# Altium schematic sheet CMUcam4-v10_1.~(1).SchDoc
size 249 x 186 mm
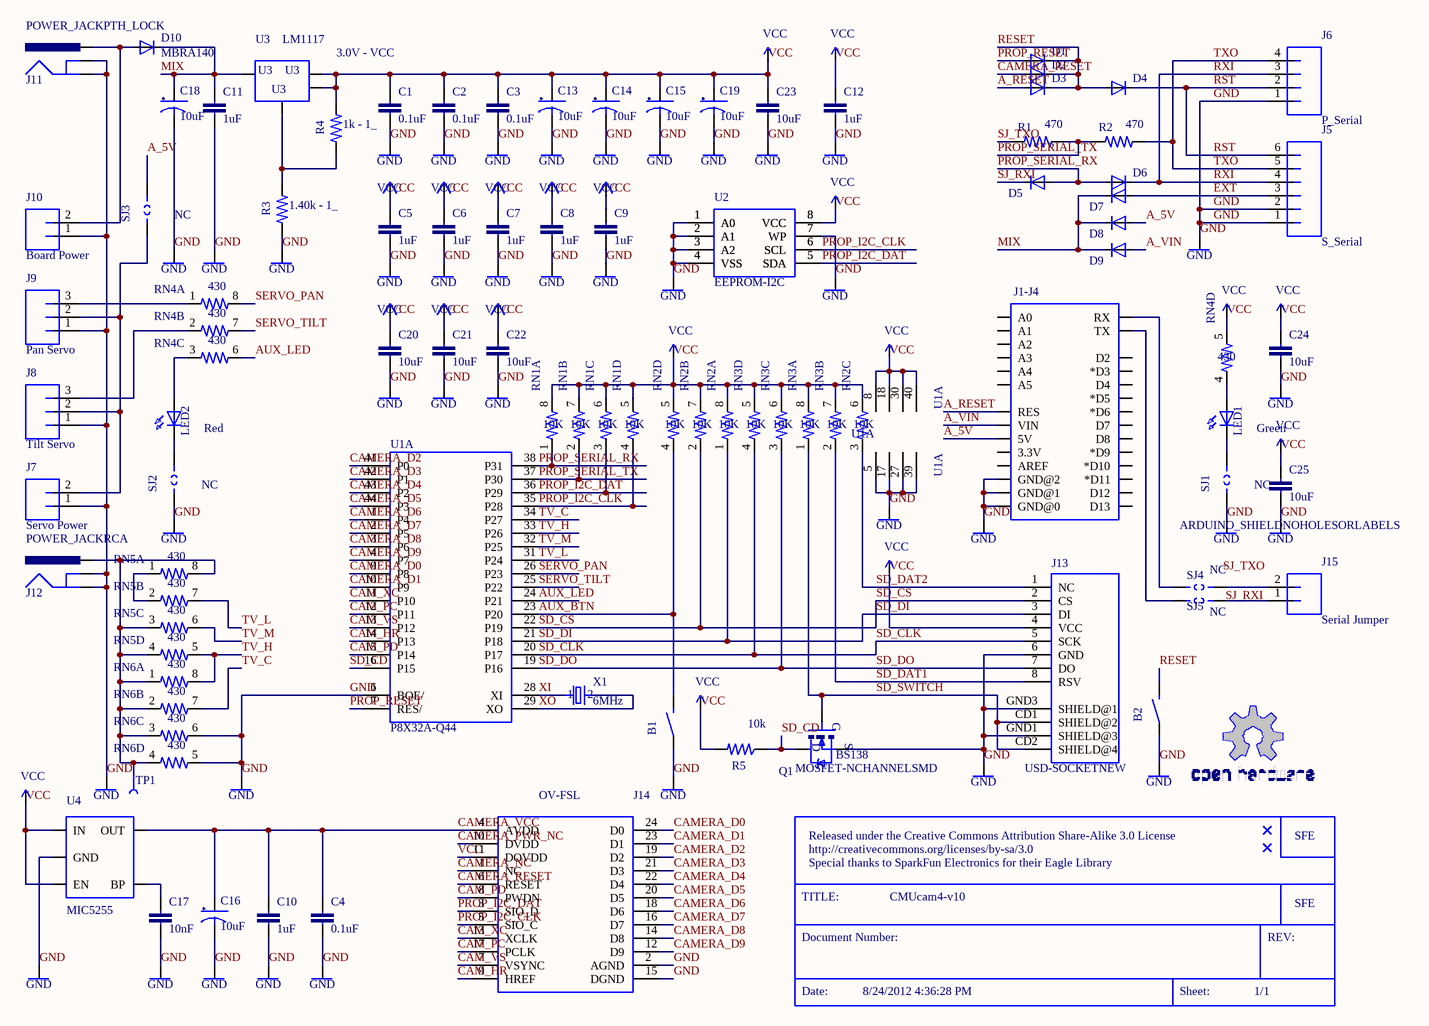
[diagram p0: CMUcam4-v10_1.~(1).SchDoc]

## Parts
(Parts that share a designator on the sheet are numbered #1, #2 ... from top to bottom, then left to right.)
B1  (no value)  [TACTILE_SWITCH_SMD]
B2  (no value)  [TACTILE_SWITCH_SMD]
C1  0.1uF  [0402-CAP]
C2  0.1uF  [0402-CAP]
C3  0.1uF  [0402-CAP]
C4  0.1uF  [0402-CAP]
C5  1uF  [0402-CAP]
C6  1uF  [0402-CAP]
C7  1uF  [0402-CAP]
C8  1uF  [0402-CAP]
C9  1uF  [0402-CAP]
C10  1uF  [0402-CAP]
C11  1uF  [0402-CAP]
C12  1uF  [0402-CAP]
C13  10uF  [EIA3216]
C14  10uF  [EIA3216]
C15  10uF  [EIA3216]
C16  10uF  [EIA3216]
C17  10nF  [0402-CAP]
C18  10uF  [EIA3216]
C19  10uF  [EIA3216]
C20  10uF  [0402-CAP]
C21  10uF  [0402-CAP]
C22  10uF  [0402-CAP]
C23  10uF  [0402-CAP]
C24  10uF  [0402-CAP]
C25  10uF  [0402-CAP]
D1  (no value)  [SOD523]
D2  (no value)  [SOD523]
D3  (no value)  [SOD523]
D4  (no value)  [SOD523]
D5  (no value)  [SOD523]
D6  (no value)  [SOD523]
D7  (no value)  [SMA-DIODE]
D8  (no value)  [SMA-DIODE]
D9  (no value)  [SMA-DIODE]
D10  MBRA140  [SMA-DIODE]
FRAME1  (no value)  (parts A,B of 2)
GND1  GND
GND2  GND
GND3  GND
GND4  GND
GND5  GND
GND6  GND
GND7  GND
GND8  GND
GND9  GND
GND10  GND
GND11  GND
GND12  GND
GND13  GND
GND14  GND
GND15  GND
GND16  GND
GND17  GND
GND18  GND
GND19  GND
GND20  GND
GND21  GND
GND22  GND
GND23  GND
GND24  GND
GND25  GND
GND26  GND
GND27  GND
GND28  GND
GND29  GND
GND30  GND
GND31  GND
GND32  GND
GND33  GND
GND34  GND
GND35  GND
GND36  GND
GND37  GND
GND38  GND
GND39  GND
J1-J4  ARDUINO_SHIELDNOHOLESORLABELS  [DUEMILANOVE_SHIELD_NOHOLES_NOLABELS]
J5  S_Serial  [1X06]
J6  P_Serial  [1X04]
J7  Servo Power  [1X02]
J8  Tilt Servo  [1X03]
J9  Pan Servo  [1X03]
J10  Board Power  [1X02]
J11  POWER_JACKPTH_LOCK  [POWER_JACK_PTH_LOCK]
J12  POWER_JACKRCA  [RCA]
J13  USD-SOCKETNEW  [MICRO-SD-SOCKET-PP]
J14  OV-FSL  [OV-FSL]
J15  Serial Jumper  [1X02]
JP1  (no value)  [SFE-NEW-WEBLOGO]
JP2  (no value)  [SFE-LOGO-FLAME]
JP3  (no value)  [MICRO-FIDUCIAL]
JP4  (no value)  [MICRO-FIDUCIAL]
LED1  Green  [LED-0603]
LED2  Red  [LED-0603]
P1  VCC
P2  VCC
P3  VCC
P4  VCC
P5  VCC
P6  VCC
P7  VCC
P8  VCC
P9  VCC
P10  VCC
P11  VCC
P12  VCC
P13  VCC
P14  VCC
P15  VCC
P16  VCC
P17  VCC
P18  VCC
P19  VCC
Q1  MOSFET-NCHANNELSMD  [SOT23-3]
R1  470  [0402-RES]
R2  470  [0402-RES]
R3  1.40k - 1_  [0402-RES]
R4  1k - 1_  [0402-RES]
R5  10k  [0402-RES]
RN1  10K  [0603-ARV]  (parts A,B,C,D of 4)
RN2  10K  [0603-ARV]  (parts A,B,C,D of 4)
RN3  10K  [0603-ARV]  (parts A,B,C,D of 4)
RN4  430  [0603-ARV]  (parts A,B,C,D of 4)
RN5  430  [0603-ARV]  (parts A,B,C,D of 4)
RN6  430  [0603-ARV]  (parts A,B,C,D of 4)
SJ1  NC  [SJ_2S-TRACE]
SJ2  NC  [SJ_2S-TRACE]
SJ3  NC  [SJ_2S-NO]
SJ4  NC  [SJ_2S-TRACE]
SJ5  NC  [SJ_2S-TRACE]
STD1  (no value)  [STAND-OFF]
STD2  (no value)  [STAND-OFF]
STD3  (no value)  [STAND-OFF]
STD4  (no value)  [STAND-OFF]
TP1  (no value)  [PAD.03X.03]
U1#1  (no value)  [P8X32A-Q44]  (part A of 2)
U1#2  P8X32A-Q44  [P8X32A-Q44]  (part A of 2)
U2  EEPROM-I2C  [SO08-EIAJ]
U3  LM1117  [SOT223]
U4  MIC5255  [SOT23-5]
U$1  (no value)  [OSHW-LOGO-M]
X1  6MHz  [HC49UP]

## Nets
A_5V: D8.A J1-J4.5V SJ3.2
A_RESET: D3.A J1-J4.RES
A_VIN: D9.A J1-J4.VIN
AUX_BTN: B1.3 RN2.4 U1#2.23(P20)
AUX_LED: RN4.6 U1#2.24(P21)
CAM_HR: J14.9(HREF) U1#2.14(P13)
CAM_PC: J14.17(PCLK) U1#2.12(P11)
CAM_PD: J14.8(PWDN) U1#2.15(P14)
CAM_VS: J14.7(VSYNC) U1#2.13(P12)
CAM_XC: J14.13(XCLK) U1#2.11(P10)
CAMERA_D0: J14.24(D0) U1#2.9(P8)
CAMERA_D1: J14.23(D1) U1#2.10(P9)
CAMERA_D2: J14.19(D2) U1#2.41(P0)
CAMERA_D3: J14.21(D3) U1#2.42(P1)
CAMERA_D4: J14.22(D4) U1#2.43(P2)
CAMERA_D5: J14.20(D5) U1#2.44(P3)
CAMERA_D6: J14.18(D6) U1#2.1(P4)
CAMERA_D7: J14.16(D7) U1#2.2(P5)
CAMERA_D8: J14.14(D8) U1#2.3(P6)
CAMERA_D9: J14.12(D9) U1#2.4(P7)
CAMERA_NC: J14.1(NC)
CAMERA_PWR_NC: J14.10(DVDD)
CAMERA_RESET: D2.A J14.6(RESET)
CAMERA_VCC: C4.1 C10.1 C16.A(+) J14.4(AVDD) U4.5(OUT)
EXT: D7.A J5.3
GND: B1.1 B2.1 C1.2 C2.2 C3.2 C4.2 C5.2 C6.2 C7.2 C8.2 C9.2 C10.2 C11.2 C12.2 C13.C(-) C14.C(-) C15.C(-) C16.C(-) C17.2 C18.C(-) C19.C(-) C20.2 C21.2 C22.2 C23.2 C24.2 C25.2 GND1.0(GND) GND2.0(GND) GND3.0(GND) GND4.0(GND) GND5.0(GND) GND6.0(GND) GND7.0(GND) GND8.0(GND) GND9.0(GND) GND10.0(GND) GND11.0(GND) GND12.0(GND) GND13.0(GND) GND14.0(GND) GND15.0(GND) GND16.0(GND) GND17.0(GND) GND18.0(GND) GND19.0(GND) GND20.0(GND) GND21.0(GND) GND22.0(GND) GND23.0(GND) GND24.0(GND) GND25.0(GND) GND26.0(GND) GND27.0(GND) GND28.0(GND) GND29.0(GND) GND30.0(GND) GND31.0(GND) GND32.0(GND) GND33.0(GND) GND34.0(GND) GND35.0(GND) GND36.0(GND) GND37.0(GND) GND38.0(GND) GND39.0(GND) J1-J4.GND@0 J1-J4.GND@1 J1-J4.GND@2 J5.1 J5.2 J6.1 J7.1 J8.1 J9.1 J10.1 J11.GND J11.GNDBREAK J12.BARREL(GND) J12.SPRING(GNDBREAK) J13.6(GND) J13.GND1(SHIELD@3) J13.GND3(SHIELD@1) J14.2(AGND) J14.15(DGND) Q1.2(S) R3.1 RN6.5 RN6.6 SJ1.1 SJ2.1 U1#1.5(VSS@1) U1#1.17(VSS@2) U1#1.27(VSS@3) U1#1.39(VSS@4) U1#2.6(BOE/) U2.1(A0) U2.2(A1) U2.3(A2) U2.4(VSS) U2.7(WP) U4.2(GND)
MIX: C11.1 C18.A(+) D7.C D8.C D9.C D10.C U3.3(IN)
PROP_I2C_CLK: J14.5(SIO_C) RN1.4 U1#2.35(P28) U2.6(SCL)
PROP_I2C_DAT: J14.3(SIO_D) RN1.3 U1#2.36(P29) U2.5(SDA)
PROP_RESET: D1.A U1#2.7(RES/)
PROP_SERIAL_RX: D5.A D6.A RN1.1 U1#2.38(P31)
PROP_SERIAL_TX: R1.2 R2.1 RN1.2 U1#2.37(P30)
RESET: B2.3 D1.C D2.C D3.C D4.A
RST: D4.C J5.6 J6.2
RXI: D6.C J5.4 J6.3
SD_CD: Q1.3(D) R5.1 U1#2.16(P15)
SD_CLK: J13.5(SCK) RN3.4 U1#2.20(P17)
SD_CS: J13.2(CS) J13.3(DI) RN2.1 RN2.2 U1#2.21(P18) U1#2.22(P19)  [also labelled SD_DI]
SD_DAT1: J13.8(RSV) RN3.2
SD_DAT2: J13.1(NC) RN2.3
SD_DO: J13.7(DO) RN3.3 U1#2.19(P16)
SD_SWITCH: J13.CD1(SHIELD@2) J13.CD2(SHIELD@4) Q1.1(G) RN3.1
SERVO_PAN: RN4.8 U1#2.26(P23)
SERVO_TILT: RN4.7 U1#2.25(P22)
SJ_RXI: D5.C
SJ_TXO: R1.1
TV_C: RN6.7 U1#2.34(P27)
TV_H: RN5.5 RN6.8 U1#2.33(P26)
TV_L: RN5.7 U1#2.31(P24)
TV_M: RN5.6 U1#2.32(P25)
TXO: J5.5 J6.4 R2.2
VCC: C1.1 C2.1 C3.1 C5.1 C6.1 C7.1 C8.1 C9.1 C12.1 C13.A(+) C14.A(+) C15.A(+) C19.A(+) C20.1 C21.1 C22.1 C23.1 C24.1 C25.1 J13.4(VCC) J14.11(DOVDD) P1.0(VCC) P2.0(VCC) P3.0(VCC) P4.0(VCC) P5.0(VCC) P6.0(VCC) P7.0(VCC) P8.0(VCC) P9.0(VCC) P10.0(VCC) P11.0(VCC) P12.0(VCC) P13.0(VCC) P14.0(VCC) P15.0(VCC) P16.0(VCC) P17.0(VCC) P18.0(VCC) P19.0(VCC) R4.2 R5.2 RN1.5 RN1.6 RN1.7 RN1.8 RN2.5 RN2.6 RN2.7 RN2.8 RN3.5 RN3.6 RN3.7 RN3.8 RN4.5 U1#1.8(VDD@1) U1#1.18(VDD@2) U1#1.30(VDD@3) U1#1.40(VDD@4) U2.8(VCC) U3.2(OUT) U3.4(OUT@1) U4.1(IN) U4.3(EN)
XI: U1#2.28(XI) X1.1
XO: U1#2.29(XO) X1.2
NetC17_1: C17.1 U4.4(BP)
NetD10_A: D10.A J10.2 J11.PWR
NetJ1-J4_RX: J1-J4.RX SJ4.1
NetJ1-J4_TX: J1-J4.TX SJ5.1
NetJ7_2: J7.2 J8.2 J9.2 SJ3.1
NetJ8_3: J8.3 RN4.2
NetJ9_3: J9.3 RN4.1
NetJ12_BREAK: J12.BREAK(PWR) RN5.3 RN5.4 RN5.8 RN6.1 RN6.2 RN6.3 RN6.4 TP1.P$1
NetJ15_1: J15.1 SJ5.2
NetJ15_2: J15.2 SJ4.2
NetLED1_A: LED1.A RN4.4
NetLED1_C: LED1.C SJ1.2
NetLED2_A: LED2.A RN4.3
NetLED2_C: LED2.C SJ2.2
NetR3_2: R3.2 R4.1 U3.1(ADJ)
NetRN5_1: RN5.1 RN5.2

Not connected (* = marked no-connect by the designer): J1-J4 3.3V A0 A1 A2 A3 A4 A5 AREF D2 D3(*D3) D4 D5(*D5) D6(*D6) D7 D8 D9(*D9) D10(*D10) D11(*D11) D12 D13

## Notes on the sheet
- 3.0V - VCC
- (near Q1) BS138
- Released under the Creative Commons Attribution Share-Alike 3.0 License
- http://creativecommons.org/licenses/by-sa/3.0
- Special thanks to SparkFun Electronics for their Eagle Library
- Labels drawn without touching a wire or pin: SJ_RXI, SJ_TXO

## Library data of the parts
B1 B2 = SWITCH-MOMENTARY-2SMD
C1-C12 C17 C20-C25 = CAP0402-CAP
C13-C16 C18 C19 = CAP_POL1206
D1-D6 = DIODESOD523
D7-D10 = DIODESMA
FRAME1 = LETTER_L
J5 = M06SIP
J6 = M04PTH
J7 J10 J15 = M02PTH
J8 J9 = M03PTH
JP1 = LOGO-SFENEW
JP2 = LOGO-SFESK
JP3 JP4 = FIDUCIALUFIDUCIAL
LED1 LED2 = LED0603
R1-R5 = RESISTOR0402-RES
RN1-RN6 = 4R-N0603-ARV
SJ1 SJ2 SJ4 SJ5 = SOLDERJUMPERTRACE
SJ3 = SOLDERJUMPERNO
STD1-STD4 = STAND-OFF
TP1 = TEST-POINT3
U1#1 = P8X32A-Q44
U3 = V_REG_LM1117SOT223
U4 = V_REG_LDOSMD
U$1 = OSHW-LOGOM
X1 = CRYSTALHC49UP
